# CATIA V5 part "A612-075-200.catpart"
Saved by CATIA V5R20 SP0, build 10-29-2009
Part number: A612-075-200
Source: Unknown
Property "A": "25.000"
Property "ARTICLENO": "A612-075-200"
Property "B": "35.000"
Property "BOMINFO": "A612-075-200"
Property "CODE": "A612-075-200"
Property "D": "17.500"
Property "FORM": "A"
Property "L": "200.000"
Property "L1": "45.000"
Property "L2": "110.000"
Property "L3": "0.000"
Property "LINA": "A612-075-200"
Property "NB": "A612-075-200"
Property "NBSYN": "$CODE."
Property "NN": "A612"
Property "NT": "CDI 3357 E-Type Wear Plates, steel and self-lubricating"
Property "SUPPLIER": "CF"
Property "T": "25.000"
Property "W": "75.000"
Bounding box of the stored display mesh (mm): x 0 to 25, y 0 to 200, z 0 to 75
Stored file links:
  C:\Users\Utente\Desktop\3D files A612\A612-075-200.catpart
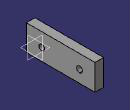
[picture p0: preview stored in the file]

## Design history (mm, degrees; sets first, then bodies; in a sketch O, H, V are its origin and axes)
Body1 "Geometry.1" (main body)
  Solid1 "A612-075-200.catpart": solid without history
